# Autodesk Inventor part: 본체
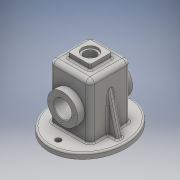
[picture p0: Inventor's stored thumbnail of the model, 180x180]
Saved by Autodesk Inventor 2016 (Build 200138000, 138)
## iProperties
Created: 2017-07
Part Number: 본체
Material: 일반
Document SubType Name: Modeling
Designer: USER
Density: 1 g/cm^3
Appearance: 기본값
Author: USER
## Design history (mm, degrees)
sketch "스케치1"
  geometry: L1 (0, 0)-(74, 0); L2 (74, 0)-(74, 100); L3 (74, 100)-(0, 100); L4 (0, 100)-(0, 0)
  constraints: 8 end point, 2 parallel, 1 horizontal, 1 perpendicular
  dimensions: "d0" = 74 distance between parallel lines of L2 L4; "d1" = 100 distance between parallel lines of L1 L3
extrude "돌출1" new body sketch "스케치1" stored distance "d2" = 74; taper "d3" = 0 deg
node "작업 평면1"
sketch "스케치2"
  geometry: L1 (17, 17)-(57, 17); L2 (57, 17)-(57, 57); L3 (57, 57)-(17, 57); L4 (17, 57)-(17, 17); L5 (0, 74)-(74, 74) reference; L6 (74, 74)-(74, 0) reference; 4 further points
  constraints: 8 end point, 3 midpoint, 2 parallel, 1 horizontal, 1 horizontal alignment, 1 perpendicular, 1 vertical alignment
  dimensions: "d5" = 40 distance between parallel lines of L2 L4; "d6" = 40 distance between parallel lines of L1 L3
extrude "돌출2" join sketch "스케치2" stored distance "d8" = 74; taper "d9" = 0 deg
sketch "스케치3"
  geometry: L1 (37, -37)-(-28, -37); L2 (37, -37)-(37, 38); L3 (0, -74)-(74, -74) reference; L4 (0, -74)-(0, 0) reference; 4 further points; 1 other entity
  constraints: 4 end point, 2 midpoint, 2 vertical, 1 coincident, 1 horizontal, 1 horizontal alignment, 1 vertical alignment, 4 other
  dimensions: "d10" = 65 distance of L1.start L1.end; "d11" = 75 distance of L1.start L2.end
extrude "돌출3" join sketch "스케치3" distance "d12" = 10; taper "d13" = 0 deg
sketch "스케치4"
  geometry: L1 (102, 110)-(-28, 110) reference; C1 r 27.5 at (37, 55); 2 further points
  constraints: 1 centre point, 1 midpoint, 1 vertical alignment
  dimensions: "d14" = 55 diameter of C1; "d15" = 55 distance from line of L1 C1.centre
extrude "돌출4" join sketch "스케치4" distance "d16" = 13; taper "d17" = 0 deg
sketch "스케치5"
  geometry: C1 r 27.5 at (37, -55) reference; C2 r 27.5 at (37, -55); 1 further point
  constraints: 1 centre point, 1 coincident
  dimensions: "d18" = 55 diameter of C2
extrude "돌출5" join sketch "스케치5" distance "d19" = 13; taper "d20" = 0 deg
node "작업 평면2"
sketch "스케치6"
  geometry: L1 (74, 100)-(0, 100) reference; L2 (74, 0)-(74, 100) reference; L3 (0, 100)-(0, 0) reference; L4 (-38, -10)-(112, -10) reference; L5 (112, 0)-(-38, 0) reference; L6 (69, -10)-(5, -10); L7 (87, 17.5)-(87, 72.5) reference; L8 (-13, 72.5)-(-13, 17.5) reference; L9 (5, -10)-(5, 95); L10 (5, 95)-(69, 95); L11 (69, 95)-(69, -10); 1 further point
  constraints: 8 end point, 2 point on line
  dimensions: "d76" = 5 distance between parallel lines of L10 L1; "d77" = 5 distance between parallel lines of L9 L3; "d78" = 5 distance between parallel lines of L2 L11
extrude "돌출6" cut sketch "스케치6" stored distance "d41" = 64; taper "d42" = 0 deg
sketch "스케치9"
  geometry: L1 (74, 74)-(74, 0) reference; C1 r 14 at (37, 37); 2 further points
  constraints: 1 centre point, 1 horizontal alignment, 1 midpoint, 1 vertical alignment
  dimensions: "d49" = 28 diameter of C1
extrude "돌출9" cut sketch "스케치9" distance "d50" = 4; taper "d51" = 0 deg
sketch "스케치10"
  geometry: C1 r 14 at (0, 0) reference; C2 r 10.5 at (0, 0); 1 further point
  constraints: 1 centre point, 1 coincident
  dimensions: "d52" = 21 diameter of C2
extrude "돌출10" cut sketch "스케치10" stored distance "d53" = 4; taper "d54" = 0 deg
sketch "스케치11" dims "d55" = 45
  geometry: C1 r 27.5 at (0, 0) reference; 3 further points
  constraints: 1 coincident, 1 vertical alignment, 2 other
hole "구멍1" sketch "스케치11" at (0, -22.5) diameter "d56" = 3.242; stored, may be unused: countersink angle "d60" = 90 deg, drill point angle "d62" = 118 deg; dims "d57" = 8, "d58" = 4, "d59" = 2, "d61" = 10
node "작업 평면3"
sketch "스케치12"
  geometry: L1 (-23, -37)-(-37, -37); C1 r 5 at (-37, 21); C2 r 5 at (-37, -95); 1 further point
  constraints: 2 centre point, 2 end point, 2 vertical alignment, 1 horizontal, 1 horizontal alignment, 1 other
  dimensions: "d67" = 10 diameter of C1; "d68" = 10 diameter of C2; "d69" = 116 distance of C2.centre C1.centre; "d70" = 58 distance of C1.centre L1.end
extrude "돌출11" cut sketch "스케치12" stored distance "d71" = 4; taper "d72" = 0 deg
fillet "모깎기1" dims "d73" = 8
sketch "스케치14"
  geometry: C1 r 27.5 at (32, -55) reference; C2 r 27.5 at (32, -55); 1 further point
  constraints: 1 centre point, 1 coincident
  dimensions: "d79" = 55 diameter of C2
extrude "돌출12" join sketch "스케치14" distance "d80" = 7; taper "d81" = -45 deg
sketch "스케치15"
  geometry: C1 r 27.5 at (32, -50) reference; C2 r 27.5 at (32, -50); 1 further point
  constraints: 1 centre point, 1 coincident
  dimensions: "d82" = 55 diameter of C2
extrude "돌출13" join sketch "스케치15" distance "d83" = 7; taper "d84" = -45 deg
sketch "스케치16"
  geometry: C1 r 27.5 at (0, 0) reference; C2 r 16 at (0, 0); 1 further point
  constraints: 1 centre point, 1 coincident
  dimensions: "d85" = 32 diameter of C2
extrude "돌출14" cut sketch "스케치16" stored distance "d86" = 7; taper "d87" = 0 deg
fillet "모깎기2" dims "d91" = 3
fillet "모깎기3" dims "d92" = 3
chamfer "모따기1" distance "d93" = 1; stored, may be unused: second distance "d94" = 2, angle "d95" = 45 deg
fillet "모깎기4" dims "d96" = 3
fillet "모깎기5" dims "d97" = 0.5
fillet "모깎기6" dims "d98" = 3
fillet "모깎기7" dims "d99" = 0.5
node "작업 평면5"
sketch "스케치17"
  geometry: L1 (-37, 3)-(-37, 92) reference; L2 (37, 92)-(37, 3) reference; L3 (-37, 72.194)-(-55, 0); L4 (37, 72.194)-(55, 0); L5 (-65, -10)-(65, -10) reference; L6 (-65, -10)-(-65, 44.039); L7 (65, -10)-(65, 47.5); L8 (-37, 72.194)-(-37, 0); L9 (-29, 0)-(-40, 0) reference; L10 (37, 72.194)-(37, 37); L11 (-55, 0)-(-37, 0); L12 (37, 37)-(55, 0); 3 further points; 1 other entity
  constraints: 16 end point, 4 point on line, 3 vertical, 1 collinear, 2 other
  dimensions: "d101" = 14 deg angle of L7 L4; "d102" = 14 deg angle of L6 L3; "d103" = 10 distance from line of L6 L3.end; "d104" = 10 distance from line of L7 L4.end; "d105" = 55 distance of L4.end point (0, 0)
extrude "돌출15" join sketch "스케치17" stored distance "d106" = 10; taper "d107" = 0 deg
node "작업 평면6"
fillet "모깎기8" dims "d109" = 3
node "솔리드1"
mirror "대칭1"
pattern_circular "원형 패턴2" dims angle "d89" = 360 deg
mirror "대칭2"
other parameters: "d21" = 0, "d66" = -37, "d100" = 37, "d108" = 0
